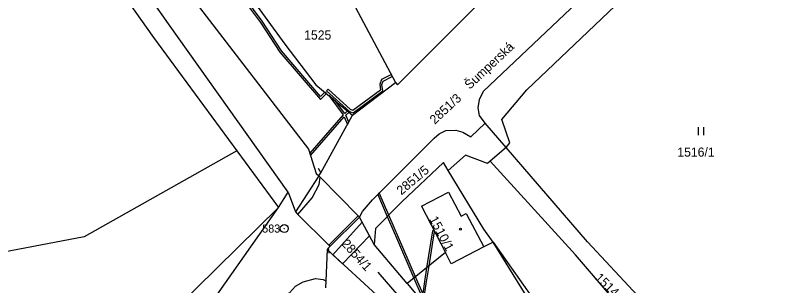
# Model space of a CAD drawing. Extents: x -562167 to -556918, y -1077891 to -1070763.
# Drawn here: x -560096.4 to -559953.4, y -1075481.6 to -1075431.3 of the extents above; entities that cross this region are included whole.
import ezdxf

# ---------------------------------------------------------------- set-up
doc = ezdxf.new("R2010")
doc.units = 0
for name, color, linetype in [('Hranice parcel', 7, 'Continuous'), ('Parcelní čísla', 7, 'Continuous'), ('Pop  PČ popisy', 7, 'Continuous'), ('Vnitřní kresba', 7, 'Continuous'), ('Věcná břemena k části', 7, 'Continuous'), ('Značky bodu BP', 7, 'Continuous'), ('Značky budov', 7, 'Continuous'), ('Značky kultur', 7, 'Continuous')]:
    doc.layers.add(name, color=color, linetype=linetype)

msp = doc.modelspace()

# ---------------------------------------------------------------- linework, layer by layer
at = {"layer": 'Hranice parcel'}
for p, q in [((-560038.81, -1075418.95), (-560025.55, -1075443.77)), ((-560033.57, -1075449.85), (-560025.55, -1075443.77)), ((-560039.49, -1075460.62), (-560033.57, -1075449.85)), ((-560004.97, -1075455.88), (-560008.87, -1075451.37)), ((-560055.13, -1075456.48), (-560047.35, -1075467.07)), ((-560004.97, -1075455.88), (-560007.95, -1075458.45)), ((-560040.33, -1075460.71), (-560039.86, -1075461.19)), ((-560039.86, -1075461.19), (-560039.49, -1075460.62)), ((-560039.86, -1075461.19), (-560044.23, -1075467.87)), ((-560047.35, -1075467.07), (-560045.55, -1075464.21)), ((-560045.55, -1075464.21), (-560044.23, -1075467.87)), ((-560029.53, -1075473.93), (-560032.27, -1075468.88)), ((-560038.32, -1075474.88), (-560038.54, -1075480.73)), ((-560023.43, -1075481.21), (-560029.53, -1075473.93)), ((-560038.54, -1075480.73), (-560038.59, -1075482.02))]:
    msp.add_line(p, q, dxfattribs=at)
for points in [[(-560045.55, -1075464.21), (-560067.84, -1075432.85), (-560097.73, -1075390.37), (-560116.01, -1075366.17), (-560124.2, -1075350.88), (-560131.1, -1075341.27), (-560136.59, -1075335.08), (-560145.89, -1075327.2), (-560154.9, -1075321.85), (-560165.27, -1075317.15), (-560182.25, -1075313.6), (-560219.76, -1075305.74), (-560242.79, -1075298.45)], [(-560154.01, -1075325.75), (-560146.95, -1075331.06), (-560140.23, -1075336.73), (-560134.57, -1075343.26), (-560127.18, -1075352.57), (-560117.89, -1075368.51), (-560100.98, -1075392.71), (-560070.64, -1075435.38), (-560055.13, -1075456.48)], [(-560131.73, -1075330.69), (-560126.56, -1075337.69), (-560119.85, -1075347.87), (-560109.4, -1075361.25), (-560084.71, -1075396.48), (-560062.73, -1075428.99), (-560041.77, -1075456.2), (-560040.33, -1075460.71)], [(-560008.87, -1075451.37), (-560009.93, -1075449.95), (-560010.17, -1075448.47), (-560009.95, -1075446.97), (-560009.18, -1075445.39), (-559985.97, -1075423.35), (-559958.28, -1075397.16), (-559945.39, -1075384.93), (-559943.86, -1075383.83), (-559942.5, -1075383.41), (-559940.64, -1075383.3), (-559938.89, -1075383.74), (-559938.31, -1075384.08)], [(-560004.97, -1075455.88), (-560004.29, -1075455), (-560005.77, -1075450.65), (-560001.12, -1075445.16), (-559973.21, -1075418.6), (-559955.84, -1075402.32)], [(-560053.5, -1075426.52), (-560046.18, -1075436.65), (-560040.41, -1075444.19), (-560033.57, -1075449.85)], [(-560025.55, -1075443.77), (-560025.22, -1075444.22), (-560007.84, -1075426.79)], [(-560032.27, -1075468.88), (-560031.7, -1075467.83), (-560029.87, -1075465.61), (-560018.39, -1075454.16), (-560017.42, -1075453.37), (-560016.17, -1075452.75), (-560014.34, -1075452.63), (-560013, -1075453.01), (-560011.51, -1075453.87), (-560008.87, -1075451.37)], [(-560055.13, -1075456.48), (-560083.55, -1075472.55), (-560102.5, -1075476.1), (-560126.48, -1075471.4)], [(-559963.49, -1075501.73), (-559989.82, -1075473.44), (-560004.97, -1075455.88)], [(-560007.95, -1075458.45), (-560008.45, -1075458.89), (-560012.51, -1075457.34), (-560015.76, -1075460.14)], [(-560015.76, -1075460.14), (-560016.65, -1075458.68), (-560024.4, -1075466), (-560029.29, -1075470.99), (-560029.53, -1075473.93)], [(-559966.29, -1075505.94), (-559992.05, -1075475.87), (-560007.95, -1075458.45)], [(-560007.4, -1075473.5), (-560009.1, -1075471.09), (-560015.76, -1075460.14)], [(-560039.86, -1075461.19), (-560039.61, -1075461.44), (-560032.51, -1075468.64), (-560032.27, -1075468.88)], [(-560087.11, -1075523.11), (-560076.53, -1075501.5), (-560066.52, -1075485.88), (-560047.35, -1075467.07)], [(-560085.45, -1075525.45), (-560069.45, -1075498.47), (-560047.35, -1075467.07)], [(-560044.23, -1075467.87), (-560043.74, -1075468.36), (-560038, -1075474.09), (-560037.78, -1075474.31)], [(-560007.4, -1075473.5), (-560009.14, -1075474.4), (-560015.19, -1075477.54), (-560016.27, -1075475.47), (-560023.43, -1075481.21)], [(-560007.4, -1075473.5), (-559982.12, -1075509.33), (-559975.39, -1075518.47)], [(-559978.25, -1075522.87), (-559992.19, -1075498.1), (-560007.4, -1075473.5)], [(-560037.78, -1075474.31), (-560038.08, -1075474.55), (-560038.32, -1075474.88)], [(-559981.4, -1075544.35), (-559983.22, -1075537.71), (-559988.35, -1075530.55), (-560001.61, -1075514.66), (-560016.02, -1075498.09), (-560028.28, -1075484.1), (-560038.32, -1075474.88)], [(-560076.53, -1075546.54), (-560078.28, -1075545.18), (-560079.3, -1075544.14), (-560079.87, -1075542.89), (-560079.8, -1075540.59), (-560078.5, -1075538.08), (-560068.09, -1075518.39), (-560059.26, -1075503.26), (-560048.86, -1075487.62), (-560045.32, -1075482.93), (-560044.19, -1075481.7), (-560042.76, -1075480.88), (-560040.5, -1075480.28), (-560039.08, -1075480.48), (-560038.54, -1075480.73)], [(-560023.43, -1075481.21), (-560016.95, -1075488.94), (-560014.22, -1075491.96), (-559982.28, -1075529.08)]]:
    msp.add_lwpolyline(points, dxfattribs=at)
at = {"layer": 'Vnitřní kresba'}
for p, q in [((-560039.96, -1075459.74), (-560039.49, -1075460.62)), ((-560039.82, -1075462.8), (-560039.61, -1075461.44)), ((-560041.07, -1075465.29), (-560039.82, -1075462.8)), ((-560020.76, -1075466.81), (-560015.69, -1075464.23)), ((-560015.69, -1075464.23), (-560013.33, -1075468.68)), ((-560043.74, -1075468.36), (-560041.07, -1075465.29)), ((-560020.76, -1075466.81), (-560016.27, -1075475.47)), ((-560038, -1075474.09), (-560032.51, -1075468.64)), ((-560037.78, -1075474.31), (-560032.27, -1075468.88)), ((-560013.33, -1075468.68), (-560012.43, -1075468.2)), ((-560012.43, -1075468.2), (-560009.14, -1075474.4)), ((-560037.94, -1075475.54), (-560038.08, -1075474.55))]:
    msp.add_line(p, q, dxfattribs=at)
at = {"layer": 'Věcná břemena k části'}
for points in [[(-560065.82, -1075410.83), (-560066.16, -1075411.05), (-560063.12, -1075416.26), (-560059.78, -1075421.54), (-560058.31, -1075423.44), (-560055.77, -1075425.81), (-560050.74, -1075432.6), (-560047.14, -1075438.12), (-560039.55, -1075446.95), (-560038.4, -1075445.85), (-560038.71, -1075445.59), (-560039.53, -1075446.37), (-560046.82, -1075437.88), (-560050.42, -1075432.38), (-560055.47, -1075425.55), (-560057.85, -1075423.32), (-560056.43, -1075422.24), (-560056.65, -1075421.92), (-560058.12, -1075423.02), (-560059.46, -1075421.32), (-560062.78, -1075416.06)], [(-560038.41, -1075445.32), (-560034.16, -1075449.17), (-560033.48, -1075449.43), (-560027.94, -1075445.36), (-560028.09, -1075444.13), (-560027.88, -1075443.53), (-560026.18, -1075442.69), (-560026.15, -1075442.66), (-560026.34, -1075442.29), (-560026.42, -1075442.36), (-560028.2, -1075443.25), (-560028.51, -1075444.09), (-560028.36, -1075445.18), (-560033.54, -1075448.98), (-560033.94, -1075448.83), (-560038.14, -1075445.03)], [(-560035.32, -1075449.82), (-560041.54, -1075456.93), (-560041.39, -1075457.38), (-560035.12, -1075450.2), (-560034.52, -1075451.58), (-560034.28, -1075451.14), (-560034.82, -1075449.88), (-560034.21, -1075449.32), (-560034.52, -1075449.06), (-560035.03, -1075449.53), (-560036.73, -1075447.24), (-560038.01, -1075446.18)], [(-560028.89, -1075464.64), (-560027.11, -1075468.76), (-560026.81, -1075468.46), (-560028.59, -1075464.33)], [(-560027.11, -1075468.76), (-560025.41, -1075472.71), (-560022.18, -1075480.21), (-560020.62, -1075483.82), (-560020.52, -1075484.68), (-560020.05, -1075485.24), (-560020.15, -1075484.4), (-559996.29, -1075512.38), (-559982.02, -1075528.68), (-559981.79, -1075528.33), (-559995.97, -1075512.15), (-560020.21, -1075483.71), (-560019.83, -1075481.27), (-560019.31, -1075477.91), (-560018.32, -1075471.52), (-560018.44, -1075471.28), (-560018.71, -1075471.42), (-560019.77, -1075478.28), (-560020.17, -1075480.82), (-560020.51, -1075483.05), (-560021.85, -1075479.95), (-560024.02, -1075474.92), (-560026.81, -1075468.46)], [(-560037.27, -1075475.85), (-560035.42, -1075477.54), (-560030.39, -1075472.35), (-560031.78, -1075469.78)]]:
    msp.add_lwpolyline(points, close=True, dxfattribs=at)
at = {"layer": 'Značky bodu BP'}
for radius in [0.75, 0.03]:
    msp.add_circle((-560046.3, -1075470.98), radius, dxfattribs=at)
at = {"layer": 'Značky budov'}
msp.add_circle((-560013.49, -1075471.09), 0.175, dxfattribs=at)
at = {"layer": 'Značky kultur'}
for p, q in [((-559969.13, -1075453.58), (-559969.13, -1075452.08)), ((-559968.13, -1075453.58), (-559968.13, -1075452.08)), ((-560028.88, -1075479.13), (-560024.95, -1075483.66))]:
    msp.add_line(p, q, dxfattribs=at)

# ---------------------------------------------------------------- texts
at = {"layer": 'Parcelní čísla'}
for s, p in [('1525', (-560042.59, -1075435.79)), ('1516/1', (-559973.07, -1075457.59))]:
    msp.add_text(s, height=1.7, dxfattribs=at).set_placement(p)
for s, rotation, p in [('2851/3', 43, (-560018.24, -1075451.66)), ('2851/5', 40, (-560024.48, -1075464.83)), ('1510/1', 298, (-560019.35, -1075469.21)), ('2854/1', 312, (-560035.74, -1075473.89)), ('1514', 316, (-559988.55, -1075480.3))]:
    msp.add_text(s, height=1.7, rotation=rotation, dxfattribs=at).set_placement(p)
at = {"layer": 'Pop  PČ popisy'}
msp.add_text('Šumperská', height=1.7, rotation=43, dxfattribs=at).set_placement((-560011.75, -1075445.17))
at = {"layer": 'Značky bodu BP'}
msp.add_text('583', height=1.5, dxfattribs=at).set_placement((-560050.4, -1075471.73))

doc.saveas('drawing.dxf')
